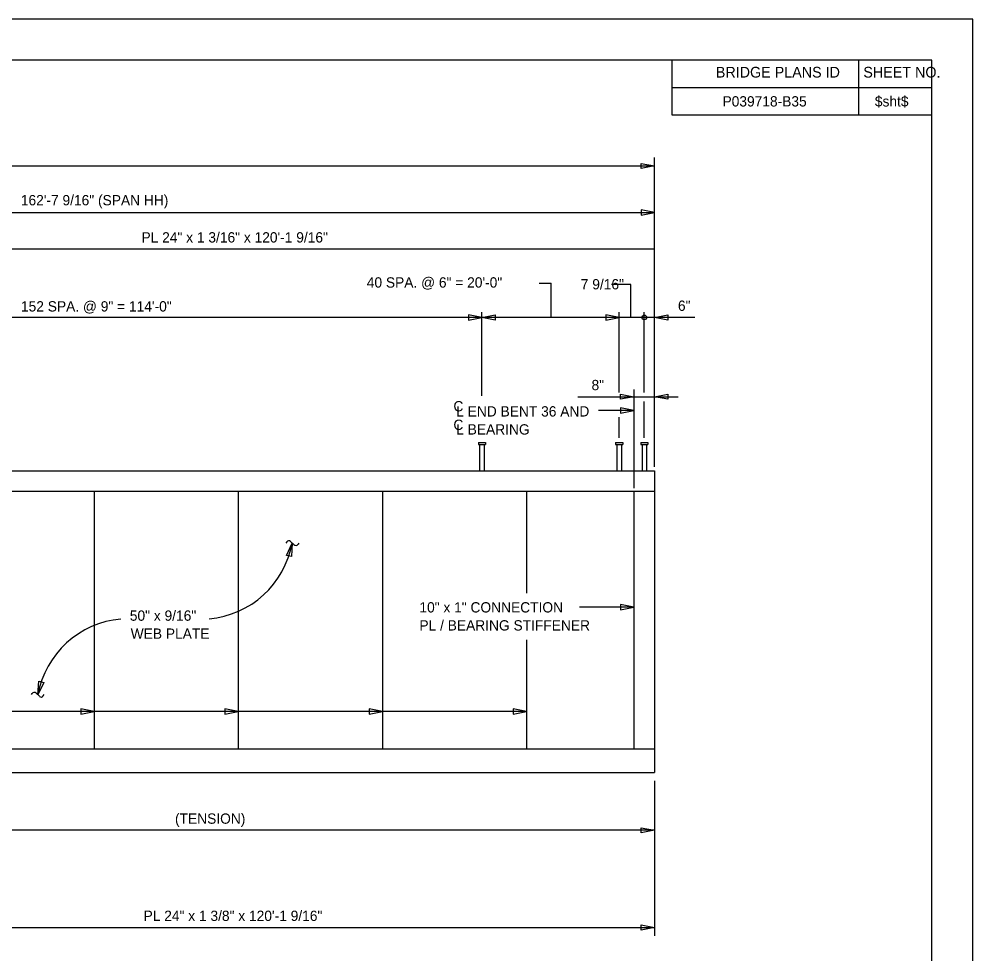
# Model space of a CAD drawing. Extents: x -305 to -161, y -187 to -99.
# Drawn here: x -207.5 to -161.18, y -144.87 to -99.49 of the extents above; entities that cross this region are included whole.
import ezdxf

# ---------------------------------------------------------------- set-up
doc = ezdxf.new("R2010")
doc.units = 0
for name, color, linetype in [('BR_AUTO DIMENSION', 7, 'Continuous'), ('BR_BORDER LINES', 7, 'Continuous'), ('BR_CENTER LINES', 7, 'Continuous'), ('BR_STRUCTURAL STEEL', 7, 'Continuous'), ('BR_TEXT', 7, 'Continuous'), ('Default', 7, 'Continuous'), ('Level 31', 7, 'Continuous')]:
    doc.layers.add(name, color=color, linetype=linetype)

msp = doc.modelspace()

# ---------------------------------------------------------------- linework, layer by layer
at = {"layer": 'BR_AUTO DIMENSION'}
for p, q in [((-176.638, -121.218), (-176.638, -106.206)), ((-285.058, -106.618), (-176.638, -106.618)), ((-230.848, -108.876), (-176.638, -108.876)), ((-176.638, -110.653), (-216.681, -110.653)), ((-182.243, -112.302), (-181.657, -112.302)), ((-181.657, -113.971), (-181.657, -112.302)), ((-177.783, -112.369), (-178.725, -112.369)), ((-177.783, -113.971), (-177.783, -112.369)), ((-185.024, -117.769), (-185.024, -113.71)), ((-178.358, -117.621), (-178.358, -113.71)), ((-177.138, -117.621), (-177.138, -113.71)), ((-178.638, -113.971), (-279.742, -113.971)), ((-174.684, -113.971), (-178.638, -113.971)), ((-180.361, -117.821), (-175.498, -117.821)), ((-177.138, -119.81), (-177.138, -118.048)), ((-177.638, -118.491), (-179.361, -118.491)), ((-178.358, -119.81), (-178.358, -118.81)), ((-177.638, -128.037), (-180.286, -128.037)), ((-182.854, -133.101), (-289.275, -133.101)), ((-176.638, -136.465), (-176.638, -143.986)), ((-176.638, -138.867), (-219.848, -138.867)), ((-216.681, -143.585), (-176.638, -143.585))]:
    msp.add_line(p, q, dxfattribs=at)
for points in [[(-177.288, -106.493), (-176.638, -106.618), (-177.288, -106.743)], [(-177.288, -109.001), (-176.638, -108.876), (-177.288, -108.751)], [(-185.674, -114.096), (-185.024, -113.971), (-185.674, -113.846)], [(-184.374, -114.096), (-185.024, -113.971), (-184.374, -113.846)], [(-179.008, -114.096), (-178.358, -113.971), (-179.008, -113.846)], [(-175.988, -114.096), (-176.638, -113.971), (-175.988, -113.846)], [(-178.288, -117.696), (-177.638, -117.821), (-178.288, -117.946)], [(-175.988, -117.946), (-176.638, -117.821), (-175.988, -117.696)], [(-178.288, -118.616), (-177.638, -118.491), (-178.288, -118.366)], [(-194.521, -125.52), (-194.238, -124.922), (-194.278, -125.582)], [(-178.288, -128.162), (-177.638, -128.037), (-178.288, -127.912)], [(-206.307, -131.689), (-206.589, -132.287), (-206.549, -131.627)], [(-204.504, -133.226), (-203.854, -133.101), (-204.504, -132.976)], [(-197.504, -133.226), (-196.854, -133.101), (-197.504, -132.976)], [(-190.504, -133.226), (-189.854, -133.101), (-190.504, -132.976)], [(-183.504, -133.226), (-182.854, -133.101), (-183.504, -132.976)], [(-177.288, -138.742), (-176.638, -138.867), (-177.288, -138.992)], [(-177.288, -143.46), (-176.638, -143.585), (-177.288, -143.71)]]:
    msp.add_lwpolyline(points, close=True, dxfattribs=at)
msp.add_circle((-177.138, -113.971), 0.111, dxfattribs=at)
for centre, start, end in [((-198.662, -124.118), 274.9624, 349.7037), ((-202.165, -133.091), 94.9624, 169.7037)]:
    msp.add_arc(centre, 4.497, start, end, dxfattribs=at)
at = {"layer": 'BR_BORDER LINES'}
for p, q in [((-163.178, -101.489), (-297.843, -101.489)), ((-175.788, -104.156), (-175.788, -101.489)), ((-166.722, -104.156), (-166.722, -101.489)), ((-163.178, -185.489), (-163.178, -101.489)), ((-175.788, -102.808), (-163.178, -102.808)), ((-166.722, -102.808), (-163.178, -102.808)), ((-163.178, -104.156), (-175.788, -104.156))]:
    msp.add_line(p, q, dxfattribs=at)
at = {"layer": 'BR_CENTER LINES'}
msp.add_line((-177.638, -117.463), (-177.638, -122.256), dxfattribs=at)
at = {"layer": 'BR_STRUCTURAL STEEL'}
for p, q in [((-216.681, -121.423), (-176.638, -121.423)), ((-176.638, -121.423), (-176.638, -122.412)), ((-285.058, -122.412), (-176.638, -122.412)), ((-203.854, -122.412), (-203.854, -134.912)), ((-196.854, -122.412), (-196.854, -134.912)), ((-189.854, -122.412), (-189.854, -134.912)), ((-182.854, -122.412), (-182.854, -127.363)), ((-177.638, -122.412), (-177.638, -134.912)), ((-176.638, -122.412), (-176.638, -134.912)), ((-182.854, -129.626), (-182.854, -134.912)), ((-285.058, -134.912), (-176.638, -134.912)), ((-176.638, -134.912), (-176.638, -136.058)), ((-216.681, -136.058), (-176.638, -136.058))]:
    msp.add_line(p, q, dxfattribs=at)
at = {"layer": 'BR_TEXT'}
for p, q in [((-194.498, -124.869), (-194.54, -124.93)), ((-194.156, -124.996), (-194.32, -124.847)), ((-193.923, -124.93), (-193.953, -124.976)), ((-206.904, -132.279), (-206.874, -132.233)), ((-206.671, -132.213), (-206.508, -132.362)), ((-206.329, -132.34), (-206.287, -132.279))]:
    msp.add_line(p, q, dxfattribs=at)
for centre, radius, start, end in [((-194.4, -124.922), 0.111, 43.4519, 151.7375), ((-194.063, -124.915), 0.125, 221.007, 330.8059), ((-206.765, -132.294), 0.125, 41.007, 150.8059), ((-206.427, -132.287), 0.111, 223.4519, 331.7375)]:
    msp.add_arc(centre, radius, start, end, dxfattribs=at)
at = {"layer": 'Default'}
for p, q in [((-185.196, -120.048), (-185.196, -120.142)), ((-185.196, -120.048), (-184.852, -120.048)), ((-185.196, -120.142), (-184.852, -120.142)), ((-185.134, -120.142), (-185.134, -121.423)), ((-184.915, -120.142), (-184.915, -121.423)), ((-184.852, -120.048), (-184.852, -120.142)), ((-178.529, -120.048), (-178.529, -120.142)), ((-178.529, -120.048), (-178.186, -120.048)), ((-178.529, -120.142), (-178.186, -120.142)), ((-178.467, -120.142), (-178.467, -121.423)), ((-178.248, -120.142), (-178.248, -121.423)), ((-178.186, -120.048), (-178.186, -120.142)), ((-177.309, -120.048), (-177.309, -120.142)), ((-177.309, -120.048), (-176.966, -120.048)), ((-177.309, -120.142), (-176.966, -120.142)), ((-177.247, -120.142), (-177.247, -121.423)), ((-177.028, -120.142), (-177.028, -121.423)), ((-176.966, -120.048), (-176.966, -120.142))]:
    msp.add_line(p, q, dxfattribs=at)
at = {"layer": 'Level 31'}
msp.add_lwpolyline([(-305.176, -187.489), (-161.176, -187.489), (-161.176, -99.489), (-305.176, -99.489)], close=True, dxfattribs=at)

# ---------------------------------------------------------------- texts
at = {"layer": 'BR_AUTO DIMENSION'}
for s, p in [('162\'-7 9/16" (SPAN HH)', (-207.417, -108.53)), ('PL 24" x 1 3/16" x 120\'-1 9/16"', (-201.557, -110.334)), ('40 SPA. @ 6" = 20\'-0"', (-190.616, -112.522)), ('7 9/16"', (-180.221, -112.609)), ('152 SPA. @ 9" = 114\'-0"', (-207.411, -113.683)), ('6"', (-175.503, -113.652)), ('8"', (-179.699, -117.502)), ('50" x 9/16" ', (-202.124, -128.694)), ('WEB PLATE', (-202.082, -129.569)), ('(TENSION)', (-199.929, -138.548)), ('PL 24" x 1 3/8" x 120\'-1 9/16"', (-201.456, -143.266))]:
    msp.add_text(s, height=0.5, rotation=360, dxfattribs=at).set_placement(p)
at = {"layer": 'BR_TEXT'}
for s, height, p in [('BRIDGE PLANS ID', 0.52, (-173.663, -102.327)), ('SHEET NO.', 0.52, (-166.499, -102.327)), ('P039718-B35', 0.5, (-173.338, -103.732)), ('$sht$', 0.5, (-165.939, -103.732))]:
    msp.add_text(s, height=height, dxfattribs=at).set_placement(p)
for s, p in [('C', (-186.407, -118.531)), ('L END BENT 36 AND', (-186.272, -118.781)), ('C', (-186.407, -119.433)), ('L BEARING', (-186.272, -119.656)), ('10" x 1" CONNECTION ', (-188.059, -128.293)), ('PL / BEARING STIFFENER', (-188.059, -129.168))]:
    msp.add_text(s, height=0.5, rotation=360, dxfattribs=at).set_placement(p)

doc.saveas('drawing.dxf')
